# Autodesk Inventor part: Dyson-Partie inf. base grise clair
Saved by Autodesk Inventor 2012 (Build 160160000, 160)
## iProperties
Created: 2012-11
Part Number: Dyson-Partie inf. base grise clair
Material: Default
Document SubType Name: Modeling
Designer: Administrateur
Density: 1 g/cm^3
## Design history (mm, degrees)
node "Dyson-Partie inf. base grise clair1"
node "Dyson-Partie inf. base grise clair"
node "Base1"
